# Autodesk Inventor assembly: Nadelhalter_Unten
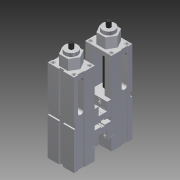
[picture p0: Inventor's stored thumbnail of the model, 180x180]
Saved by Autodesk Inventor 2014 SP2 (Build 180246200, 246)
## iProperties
Created: 2015-06
Part Number: Nadelhalter_Unten
Document SubType Name: Assembly
Designer: e_krauts
Sending System: SolidWorks 2011
Last Author: e_boekem
Author: e_krauts
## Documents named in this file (8)
- Z:\VDW-Nachwuchsstiftung Intern\Mitarbeiter Ablage\Steffen Krauth\IVCAM\KnowledgeBase Daten\NADELHALTER_UNTEN\DesignModel.iam
- Z:\VDW-Nachwuchsstiftung Intern\Mitarbeiter Ablage\Steffen Krauth\IVCAM\KnowledgeBase Daten\NADELHALTER_UNTEN\Backe20x40.ipt
- Z:\VDW-Nachwuchsstiftung Intern\Mitarbeiter Ablage\Steffen Krauth\IVCAM\KnowledgeBase Daten\NADELHALTER_UNTEN\Unterteil.ipt
- Z:\VDW-Nachwuchsstiftung Intern\Mitarbeiter Ablage\Steffen Krauth\IVCAM\KnowledgeBase Daten\NADELHALTER_UNTEN\Backe 40 x 20 ohne.ipt
- Z:\VDW-Nachwuchsstiftung Intern\Mitarbeiter Ablage\Steffen Krauth\IVCAM\KnowledgeBase Daten\NADELHALTER_UNTEN\Spindel.ipt
- Z:\VDW-Nachwuchsstiftung Intern\Mitarbeiter Ablage\Steffen Krauth\IVCAM\Nadelhalterung.ipt
- Z:\VDW-Nachwuchsstiftung Intern\Mitarbeiter Ablage\Steffen Krauth\IVCAM\KnowledgeBase Daten\NADELHALTER_UNTEN\Schraubstock.iam
- Z:\VDW-Nachwuchsstiftung Intern\Mitarbeiter Ablage\Steffen Krauth\IVCAM\KnowledgeBase Daten\NADELHALTER_UNTEN\Nadelhalterung-Unterteil_01.ipt
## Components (6 placed, 6 different names)
1. Backe20x40:1 — Passend:2, Fluchtend:1, Fluchtend:3
2. Unterteil:1 — Passend:1, Passend:2, Passend:4, Passend:5, Fluchtend:1
3. Backe 40 x 20 ohne:1 — Passend:3, Passend:4, Fluchtend:4, Fluchtend:5, Passend:6, Passend:7
4. Spindel:2 — Passend:1, Passend:3, Passend:5
5. Schraubstock:1 [sub-assembly] — Fluchtend:3, Fluchtend:4
6. Nadelhalterung-Unterteil_01:1 — Fluchtend:5, Passend:6, Passend:7
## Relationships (11: Mate 7, Flush 4)
- Passend:1 [Mate]: Unterteil:1 ↔ Spindel:2
- Passend:2 [Mate]: Backe20x40:1 ↔ Unterteil:1
- Passend:3 [Mate]: Backe 40 x 20 ohne:1 ↔ Spindel:2
- Passend:4 [Mate]: Unterteil:1 ↔ Backe 40 x 20 ohne:1
- Passend:5 [Mate]: Unterteil:1 ↔ Spindel:2
- Fluchtend:1 [Flush]: Backe20x40:1 ↔ Unterteil:1
- Fluchtend:3 [Flush]: Backe20x40:1 ↔ Schraubstock:1
- Fluchtend:4 [Flush]: Backe 40 x 20 ohne:1 ↔ Schraubstock:1
- Fluchtend:5 [Flush]: Backe 40 x 20 ohne:1 ↔ Nadelhalterung-Unterteil_01:1
- Passend:6 [Mate]: Backe 40 x 20 ohne:1 ↔ Nadelhalterung-Unterteil_01:1
- Passend:7 [Mate]: Backe 40 x 20 ohne:1 ↔ Nadelhalterung-Unterteil_01:1
